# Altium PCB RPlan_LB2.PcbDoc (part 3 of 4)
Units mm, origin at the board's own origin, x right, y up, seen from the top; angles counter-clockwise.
Board outline 38.2 x 43.28 mm, 2 copper layers (Top Layer, Bottom Layer); 36 components, 100 nets, 269 pads, 31 vias.
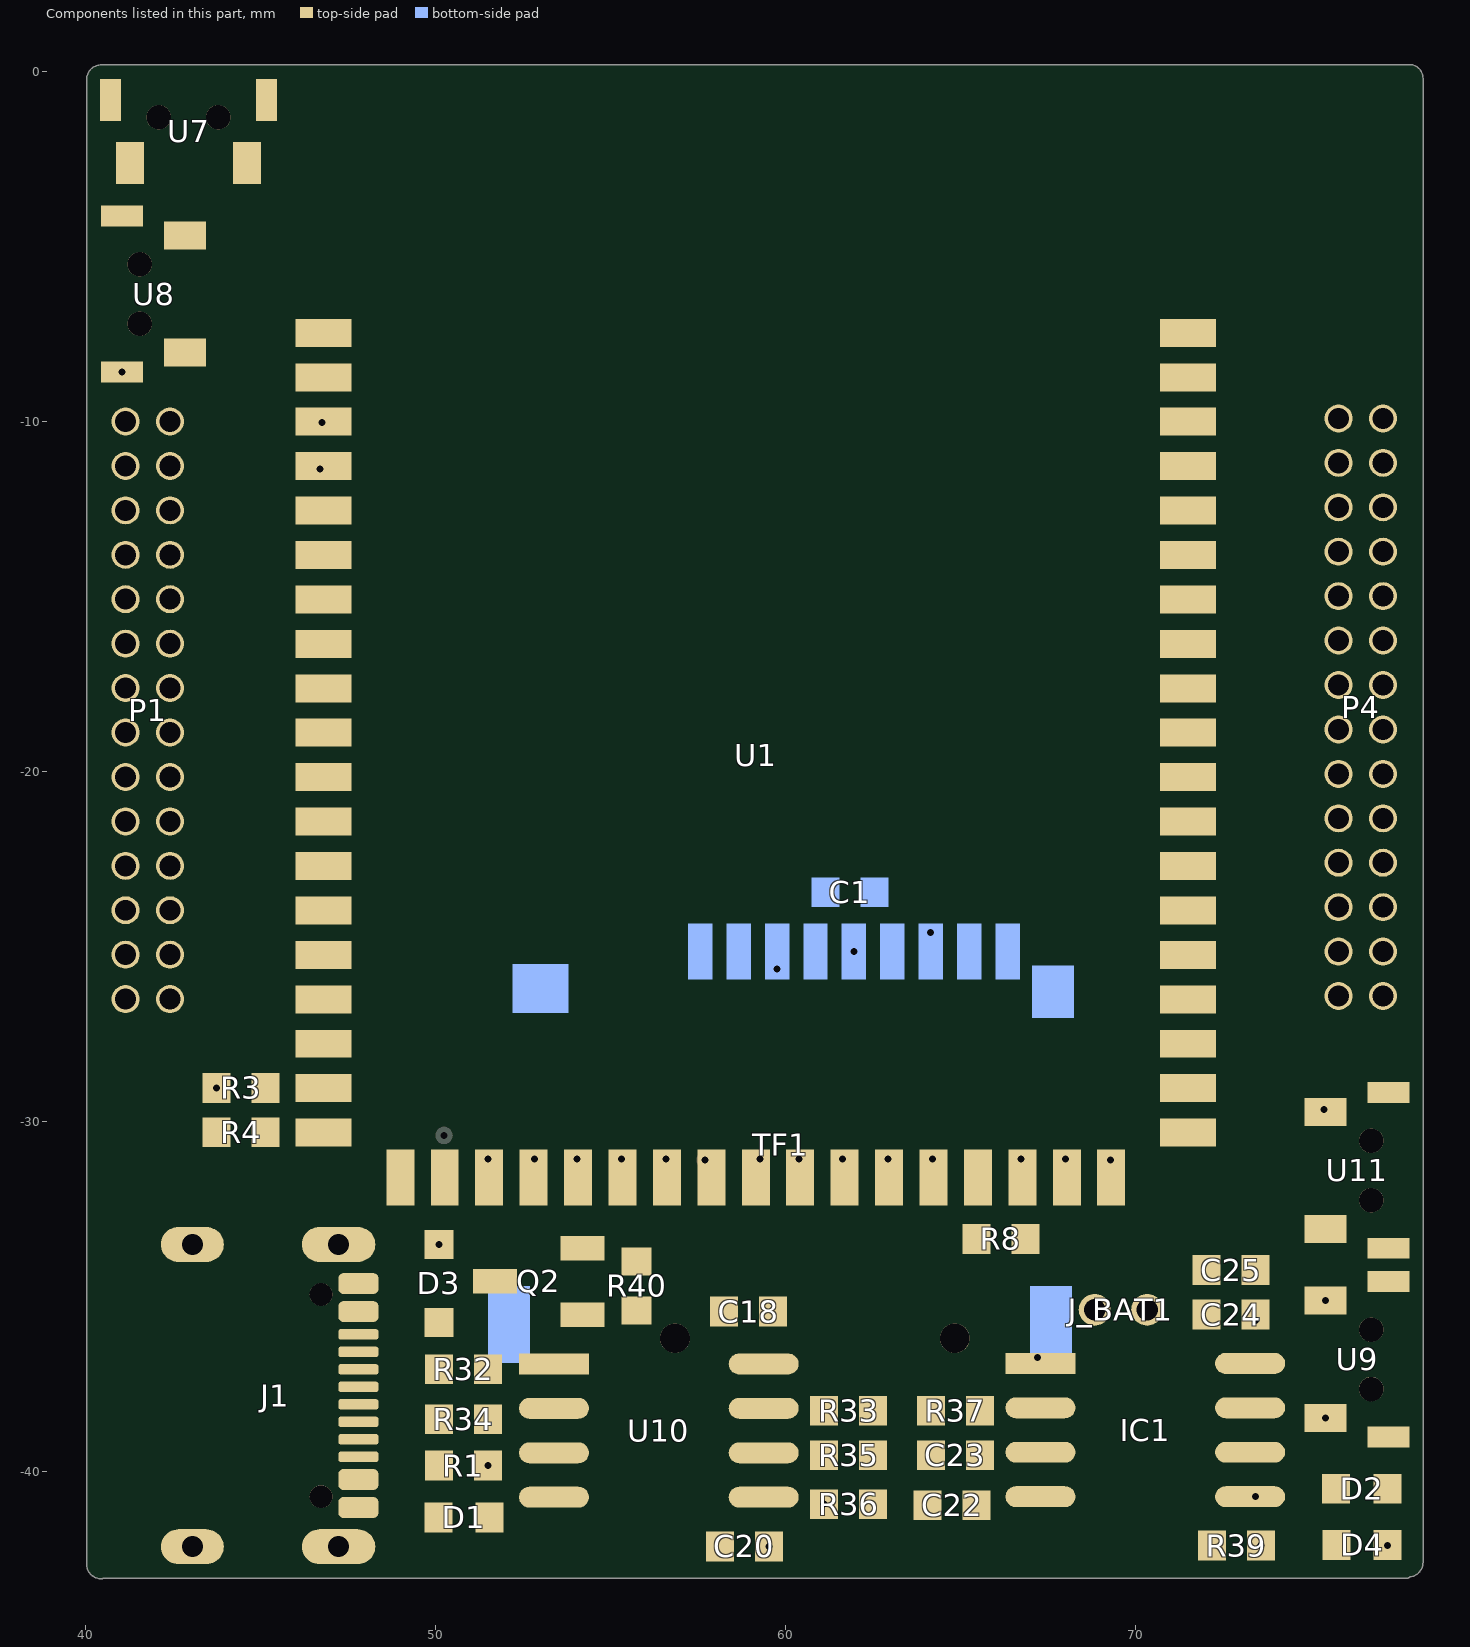
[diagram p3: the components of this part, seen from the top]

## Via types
v1: diameter 0.5, hole 0.3, Top Layer to Bottom Layer, 28 vias
v2: diameter 0.4, hole 0.2, Top Layer to Bottom Layer, 3 vias

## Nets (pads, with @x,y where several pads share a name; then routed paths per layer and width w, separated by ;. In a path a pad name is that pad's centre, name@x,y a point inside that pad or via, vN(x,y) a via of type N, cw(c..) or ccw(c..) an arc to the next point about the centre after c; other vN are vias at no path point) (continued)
copper on no net: (continued)
  Bottom Layer w0.025: 56.497,-15.715 57.386,-15.715 ; 56.497,-15.69 57.386,-15.69 ; 56.497,-15.664 57.386,-15.664 ; 56.497,-15.639 57.386,-15.639 ; 56.497,-15.613 57.386,-15.613 ; 56.497,-15.588 57.386,-15.588 ; 56.497,-15.563 57.386,-15.563 ; 56.497,-15.537 57.386,-15.537 ; 56.497,-15.512 57.386,-15.512 ; 56.497,-15.486 57.386,-15.486 ; 56.497,-15.461 57.386,-15.461 ; 56.497,-15.436 57.386,-15.436 ; 56.497,-15.41 57.183,-15.41 ; 56.497,-15.385 57.183,-15.385 ; 56.497,-15.359 57.183,-15.359 ; 56.497,-15.334 57.183,-15.334 ; 56.497,-15.309 57.183,-15.309 ; 56.497,-15.283 57.183,-15.283 ; 56.497,-15.258 57.183,-15.258 ; 56.497,-15.232 57.183,-15.232 ; 56.497,-15.207 57.183,-15.207 ; 56.497,-15.182 57.183,-15.182 ; 56.497,-15.156 57.183,-15.156 ; 56.497,-15.131 57.183,-15.131 ; 56.497,-14.775 56.852,-14.775 ; 56.497,-14.75 56.852,-14.75 ; 56.497,-14.724 56.852,-14.724 ; 56.497,-14.699 56.852,-14.699 ; 56.497,-14.674 56.852,-14.674 ; 56.497,-14.648 56.852,-14.648 ; 56.497,-14.623 56.852,-14.623 ; 56.497,-14.597 56.852,-14.597 ; 56.497,-14.572 56.852,-14.572 ; 56.497,-14.547 56.852,-14.547 ; 56.497,-14.521 56.852,-14.521 ; 56.497,-14.496 56.852,-14.496 ; 56.497,-14.47 56.852,-14.47 ; 56.497,-14.445 56.852,-14.445 ; 56.497,-14.115 56.852,-14.115 ; 56.497,-14.089 56.852,-14.089 ; 56.497,-14.064 56.852,-14.064 ; 56.497,-14.039 56.852,-14.039 ; 56.497,-14.013 56.852,-14.013 ; 56.497,-13.988 56.852,-13.988 ; 56.497,-13.962 56.852,-13.962 ; 56.497,-13.937 56.852,-13.937 ; 56.497,-13.912 56.852,-13.912 ; 56.497,-13.886 56.852,-13.886 ; 56.497,-13.861 56.852,-13.861 ; 56.497,-13.835 56.852,-13.835 ; 56.497,-13.81 56.852,-13.81 ; 56.497,-13.429 56.878,-13.429 ; 56.497,-13.404 56.852,-13.404 ; 56.497,-13.378 56.852,-13.378 ; 56.497,-13.353 56.852,-13.353 ; 56.497,-13.327 56.852,-13.327 ; 56.497,-13.302 56.852,-13.302 ; 56.497,-13.277 56.852,-13.277 ; 56.497,-13.251 56.852,-13.251 ; 56.497,-13.226 56.852,-13.226 ; 56.497,-13.2 56.852,-13.2 ; 56.497,-13.175 56.852,-13.175 ; 56.497,-13.15 56.852,-13.15 ; 56.497,-12.743 56.852,-12.743 ; 56.497,-12.718 56.852,-12.718 ; 56.497,-12.692 56.852,-12.692 ; 56.497,-12.667 56.852,-12.667 ; 56.497,-12.642 56.852,-12.642 ; 56.497,-12.616 56.852,-12.616 ; 56.497,-12.591 56.852,-12.591 ; 56.497,-12.565 56.852,-12.565 ; 56.497,-12.54 56.852,-12.54 ; 56.497,-12.515 56.852,-12.515 ; 56.497,-12.489 56.852,-12.489 ; 56.497,-12.464 56.852,-12.464 ; 56.802,-21.405 57.183,-21.405 ; 56.802,-21.379 57.183,-21.379 ; 56.802,-21.252 57.183,-21.252 ; 56.802,-21.227 57.183,-21.227 ; 56.802,-21.125 57.183,-21.125 ; 56.802,-19.525 57.183,-19.525 ; 56.802,-19.5 57.183,-19.5 ; 56.802,-19.474 57.183,-19.474 ; 56.802,-18.738 57.843,-18.738 ; 56.802,-18.712 57.843,-18.712 ; 56.802,-18.611 57.843,-18.611 ; 56.802,-18.534 57.843,-18.534 ; 56.802,-18.509 57.843,-18.509 ; 56.802,-18.484 57.843,-18.484 ; 56.802,-18.458 57.843,-18.458 ; 56.802,-12.108 57.183,-12.108 ; 56.802,-12.083 57.183,-12.083 ; 56.802,-11.829 57.183,-11.829 ; 56.802,-11.803 59.164,-11.803 ; 56.802,-11.778 59.164,-11.778 ; 56.802,-11.448 57.538,-11.448 ; 56.802,-11.422 57.538,-11.422 ; 56.802,-11.397 57.538,-11.397 ; 56.802,-11.194 57.538,-11.194 ; 56.802,-11.168 57.538,-11.168 ; 56.802,-11.143 57.538,-11.143 ; 56.802,-10.432 58.529,-10.432 ; 56.802,-10.406 58.529,-10.406 ; 56.852,-21.354 57.183,-21.354 ; 56.852,-21.328 57.183,-21.328 ; 56.852,-21.303 57.183,-21.303 ; 56.852,-21.278 57.183,-21.278 ; 56.852,-21.201 57.183,-21.201 ; 56.852,-21.176 57.183,-21.176 ; 56.852,-21.151 57.183,-21.151 ; 56.852,-20.058 57.183,-20.058 ; 56.852,-20.033 57.183,-20.033 ; 56.852,-20.008 57.183,-20.008 ; 56.852,-19.982 57.183,-19.982 ; 56.852,-19.957 57.183,-19.957 ; 56.852,-19.931 57.183,-19.931 ; 56.852,-19.906 57.183,-19.906 ; 56.852,-19.881 57.183,-19.881 ; 56.852,-19.855 57.183,-19.855 ; 56.852,-19.83 57.183,-19.83 ; 56.852,-19.804 57.183,-19.804 ; 56.852,-19.779 57.183,-19.779 ; 56.852,-19.754 57.183,-19.754 ; 56.852,-19.728 57.183,-19.728 ; 56.852,-19.703 57.183,-19.703 ; 56.852,-19.677 57.183,-19.677 ; 56.852,-19.652 57.183,-19.652 ; 56.852,-19.627 57.183,-19.627 ; 56.852,-19.601 57.183,-19.601 ; 56.852,-19.576 57.183,-19.576 ; 56.852,-19.55 57.183,-19.55 ; 56.852,-18.687 57.843,-18.687 ; 56.852,-18.661 57.843,-18.661 ; 56.852,-18.636 57.843,-18.636 ; 56.852,-18.585 57.843,-18.585 ; 56.852,-18.56 57.843,-18.56 ; 56.852,-12.057 57.183,-12.057 ; 56.852,-12.032 57.183,-12.032 ; 56.852,-12.007 57.183,-12.007 ; 56.852,-11.981 57.183,-11.981 ; 56.852,-11.956 57.183,-11.956 ; 56.852,-11.93 57.183,-11.93 ; 56.852,-11.905 57.183,-11.905 ; 56.852,-11.88 57.183,-11.88 ; 56.852,-11.854 57.183,-11.854 ; 56.852,-11.372 57.538,-11.372 ; 56.852,-11.346 57.538,-11.346 ; 56.852,-11.321 57.538,-11.321 ; 56.852,-11.295 57.538,-11.295 ; 56.852,-11.27 57.538,-11.27 ; 56.852,-11.245 57.538,-11.245 ; 56.852,-11.219 57.538,-11.219 ; 56.852,-10.457 58.529,-10.457 ; 56.852,-10.381 58.529,-10.381 ; 56.852,-10.356 58.529,-10.356 ; 56.852,-10.33 58.529,-10.33 ; 56.852,-10.305 58.529,-10.305 ; 56.852,-10.279 58.529,-10.279 ; 56.852,-10.254 58.529,-10.254 ; 56.852,-10.229 58.529,-10.229 ; 56.852,-10.203 58.529,-10.203 ; 56.852,-10.178 58.529,-10.178 ; 56.852,-10.152 58.529,-10.152 ; 56.852,-10.127 59.85,-10.127 ; 56.852,-10.102 59.85,-10.102 ; 57.157,-22.09 58.173,-22.09 ; 57.157,-22.065 58.173,-22.065 ; 57.157,-22.04 58.173,-22.04 ; 57.157,-22.014 58.173,-22.014 ; 57.157,-21.989 58.173,-21.989 ; 57.157,-21.963 58.173,-21.963 ; 57.157,-21.938 58.173,-21.938 ; 57.157,-21.913 58.173,-21.913 ; 57.157,-21.887 58.173,-21.887 ; 57.157,-21.862 58.173,-21.862 ; 57.157,-21.836 58.173,-21.836 ; 57.157,-21.811 58.173,-21.811 ; 57.157,-21.786 58.173,-21.786 ; 57.157,-21.76 58.173,-21.76 ; 57.157,-21.049 57.538,-21.049 ; 57.157,-21.024 57.538,-21.024 ; 57.157,-20.998 57.538,-20.998 ; 57.157,-20.973 57.538,-20.973 ; 57.157,-20.947 57.538,-20.947 ; 57.157,-20.922 57.538,-20.922 ; 57.157,-20.897 57.538,-20.897 ; 57.157,-20.871 57.538,-20.871 ; 57.157,-20.846 57.538,-20.846 ; 57.157,-20.82 57.538,-20.82 ; 57.157,-20.795 57.538,-20.795 ; 57.157,-20.77 57.538,-20.77 ; 57.157,-20.414 57.538,-20.414 ; 57.157,-20.389 57.538,-20.389 ; 57.157,-20.363 57.538,-20.363 ; 57.157,-20.338 57.538,-20.338 ; 57.157,-20.312 57.538,-20.312 ; 57.157,-20.287 57.538,-20.287 ; 57.157,-20.262 57.538,-20.262 ; 57.157,-20.236 57.538,-20.236 ; 57.157,-20.211 57.538,-20.211 ; 57.157,-20.185 57.538,-20.185 ; 57.157,-20.16 57.538,-20.16 ; 57.157,-20.135 57.538,-20.135 ; 57.157,-17.747 57.538,-17.747 ; 57.157,-17.722 57.538,-17.722 ; 57.157,-17.696 57.538,-17.696 ; 57.157,-17.671 57.538,-17.671 ; 57.157,-17.645 57.538,-17.645 ; 57.157,-17.62 57.538,-17.62 ; 57.157,-17.595 57.538,-17.595 ; 57.157,-17.569 57.538,-17.569 ; 57.157,-17.544 57.538,-17.544 ; 57.157,-17.518 57.538,-17.518 ; 57.157,-17.493 57.538,-17.493 ; 57.157,-17.468 57.538,-17.468 ; 57.157,-16.756 57.386,-16.756 ; 57.157,-16.731 57.386,-16.731 ; 57.157,-16.706 57.386,-16.706 ; 57.157,-16.68 57.386,-16.68 ; 57.157,-16.655 57.386,-16.655 ; 57.157,-16.629 57.386,-16.629 ; 57.157,-16.604 57.386,-16.604 ; 57.157,-16.579 57.386,-16.579 ; 57.157,-16.553 57.386,-16.553 ; 57.157,-16.528 57.386,-16.528 ; 57.157,-16.502 57.386,-16.502 ; 57.157,-16.477 57.386,-16.477 ; 57.157,-15.08 57.386,-15.08 ; 57.157,-15.055 57.386,-15.055 ; 57.157,-15.029 57.386,-15.029 ; 57.157,-15.004 57.386,-15.004 ; 57.157,-14.978 57.386,-14.978 ; 57.157,-14.953 57.386,-14.953 ; 57.157,-14.928 57.386,-14.928 ; 57.157,-14.902 57.386,-14.902 ; 57.157,-14.877 57.386,-14.877 ; 57.157,-14.851 57.386,-14.851 ; 57.157,-14.826 57.386,-14.826 ; 57.157,-14.801 57.386,-14.801 ; 57.157,-14.775 57.386,-14.775 ; 57.157,-14.75 57.386,-14.75 ; 57.157,-14.724 57.386,-14.724 ; 57.157,-14.699 57.386,-14.699 ; 57.157,-14.674 57.386,-14.674 ; 57.157,-14.648 57.411,-14.648 ; 57.157,-14.623 57.411,-14.623 ; 57.157,-14.597 57.411,-14.597 ; 57.157,-14.572 57.462,-14.572 ; 57.157,-14.547 57.462,-14.547 ; 57.157,-14.521 57.462,-14.521 ; 57.157,-14.496 57.487,-14.496 ; 57.157,-14.47 57.538,-14.47 ; 57.157,-14.445 57.538,-14.445 ; 57.157,-13.429 57.843,-13.429 ; 57.157,-13.404 57.843,-13.404 ; 57.157,-13.378 57.843,-13.378 ; 57.157,-13.353 57.843,-13.353 ; 57.157,-13.327 57.843,-13.327 ; 57.157,-13.302 57.843,-13.302 ; 57.157,-13.277 57.843,-13.277 ; 57.157,-13.251 57.843,-13.251 ; 57.157,-13.226 57.843,-13.226 ; 57.157,-13.2 57.843,-13.2 ; 57.157,-13.175 57.843,-13.175 ; 57.157,-13.15 57.843,-13.15 ; 57.157,-12.743 57.843,-12.743 ; 57.157,-12.718 57.843,-12.718 ; 57.157,-12.692 57.843,-12.692 ; 57.157,-12.667 57.843,-12.667 ; 57.157,-12.642 57.843,-12.642 ; 57.157,-12.616 57.843,-12.616 ; 57.157,-12.591 57.843,-12.591 ; 57.157,-12.565 57.843,-12.565 ; 57.157,-12.54 57.843,-12.54 ; 57.157,-12.515 57.843,-12.515 ; 57.157,-12.489 57.843,-12.489 ; 57.157,-12.464 57.843,-12.464 ; 57.157,-11.753 57.538,-11.753 ; 57.157,-11.727 57.538,-11.727 ; 57.157,-11.702 57.538,-11.702 ; 57.157,-11.676 57.538,-11.676 ; 57.157,-11.651 57.538,-11.651 ; 57.157,-11.626 57.538,-11.626 ; 57.157,-11.6 57.538,-11.6 ; 57.157,-11.575 57.538,-11.575 ; 57.157,-11.549 57.538,-11.549 ; 57.157,-11.524 57.538,-11.524 ; 57.157,-11.499 57.538,-11.499 ; 57.157,-11.473 57.538,-11.473 ; 57.157,-10.813 57.538,-10.813 ; 57.157,-10.787 57.538,-10.787 ; 57.157,-10.762 57.538,-10.762 ; 57.157,-10.737 57.538,-10.737 ; 57.157,-10.711 57.538,-10.711 ; 57.157,-10.686 57.538,-10.686 ; 57.157,-10.66 57.538,-10.66 ; 57.157,-10.635 57.538,-10.635 ; 57.157,-10.61 57.538,-10.61 ; 57.157,-10.584 57.538,-10.584 ; 57.157,-10.559 57.538,-10.559 ; 57.157,-10.533 57.538,-10.533 ; 57.157,-10.508 57.538,-10.508 ; 57.157,-10.483 57.538,-10.483 ; 57.487,-21.735 57.868,-21.735 ; 57.487,-21.709 57.843,-21.709 ; 57.487,-21.684 57.843,-21.684 ; 57.487,-21.659 57.843,-21.659 ; 57.487,-21.633 57.843,-21.633 ; 57.487,-21.608 57.843,-21.608 ; 57.487,-21.582 57.843,-21.582 ; 57.487,-21.557 57.843,-21.557 ; 57.487,-21.532 57.843,-21.532 ; 57.487,-21.506 57.843,-21.506 ; 57.487,-21.481 57.843,-21.481 ; 57.487,-21.455 57.843,-21.455 ; 57.487,-21.43 57.843,-21.43 ; 57.487,-21.405 57.843,-21.405 ; 57.487,-21.379 57.843,-21.379 ; 57.487,-21.354 57.843,-21.354 ; 57.487,-21.328 57.843,-21.328 ; 57.487,-21.303 57.843,-21.303 ; 57.487,-21.278 57.843,-21.278 ; 57.487,-21.252 57.843,-21.252 ; 57.487,-21.227 57.843,-21.227 ; 57.487,-21.201 57.843,-21.201 ; 57.487,-21.176 57.843,-21.176 ; 57.487,-21.151 57.843,-21.151 ; 57.487,-21.125 57.843,-21.125 ; 57.487,-19.754 59.519,-19.754 ; 57.487,-19.728 58.529,-19.728 ; 57.487,-19.703 58.529,-19.703 ; 57.487,-19.677 58.529,-19.677 ; 57.487,-19.652 58.529,-19.652 ; 57.487,-19.627 58.529,-19.627 ; 57.487,-19.601 58.529,-19.601 ; 57.487,-19.576 58.529,-19.576 ; 57.487,-19.55 58.529,-19.55 ; 57.487,-19.525 58.529,-19.525 ; 57.487,-19.5 58.529,-19.5 ; 57.487,-19.474 58.529,-19.474 ; 57.487,-14.42 57.564,-14.42 ; 57.487,-14.394 57.64,-14.394 ; 57.487,-14.369 57.64,-14.369 ; 57.487,-14.343 57.716,-14.343 ; 57.487,-14.318 57.843,-14.318 ; 57.487,-14.293 57.843,-14.293 ; 57.487,-14.267 57.843,-14.267 ; 57.487,-14.242 57.843,-14.242 ; 57.487,-14.216 57.843,-14.216 ; 57.487,-14.191 57.843,-14.191 ; 57.487,-14.166 57.843,-14.166 ; 57.487,-14.14 57.843,-14.14 ; 57.487,-14.115 57.843,-14.115 ; 57.487,-14.089 57.843,-14.089 ; 57.487,-14.064 57.843,-14.064 ; 57.487,-14.039 57.843,-14.039 ; 57.487,-14.013 57.843,-14.013 ; 57.487,-13.988 57.843,-13.988 ; 57.487,-13.962 57.843,-13.962 ; 57.487,-13.937 57.843,-13.937 ; 57.487,-13.912 57.843,-13.912 ; 57.487,-13.886 57.843,-13.886 ; 57.487,-13.861 57.843,-13.861 ; 57.487,-13.835 57.843,-13.835 ; 57.487,-13.81 57.843,-13.81 ; 57.487,-12.108 57.843,-12.108 ; 57.487,-12.083 57.843,-12.083 ; 57.487,-12.057 57.843,-12.057 ; 57.487,-12.032 57.843,-12.032 ; 57.487,-12.007 57.843,-12.007 ; 57.487,-11.981 57.843,-11.981 ; 57.487,-11.956 57.843,-11.956 ; 57.487,-11.93 57.843,-11.93 ; 57.487,-11.905 57.843,-11.905 ; 57.487,-11.88 57.843,-11.88 ; 57.487,-11.854 57.843,-11.854 ; 57.487,-11.829 57.843,-11.829 ; 57.614,-15.537 57.843,-15.537 ; 57.614,-15.512 57.843,-15.512 ; 57.614,-15.486 57.691,-15.486 ; 57.614,-15.461 57.64,-15.461 ; 57.614,-15.436 57.64,-15.436 ; 57.64,-15.563 57.792,-15.563 ; 57.691,-15.766 57.716,-15.766 ; 57.691,-15.74 57.716,-15.74 ; 57.691,-15.715 57.767,-15.715 ; 57.691,-15.69 57.767,-15.69 ; 57.691,-15.664 57.767,-15.664 ; 57.691,-15.639 57.767,-15.639 ; 57.691,-15.613 57.767,-15.613 ; 57.691,-15.588 57.767,-15.588 ; 57.767,-15.486 57.843,-15.486 ; 57.767,-15.461 57.843,-15.461 ; 57.767,-15.436 57.843,-15.436 ; 57.792,-17.62 58.173,-17.62 ; 57.792,-17.595 58.173,-17.595 ; 57.792,-17.569 58.173,-17.569 ; 57.843,-20.439 58.834,-20.439 ; 57.843,-20.414 58.173,-20.414 ; 57.843,-20.389 58.173,-20.389 ; 57.843,-20.363 58.173,-20.363 ; 57.843,-20.338 58.173,-20.338 ; 57.843,-20.312 58.173,-20.312 ; 57.843,-20.287 58.173,-20.287 ; 57.843,-20.262 58.173,-20.262 ; 57.843,-20.236 58.173,-20.236 ; 57.843,-20.211 58.173,-20.211 ; 57.843,-20.185 58.173,-20.185 ; 57.843,-20.16 58.173,-20.16 ; 57.843,-20.135 58.173,-20.135 ; 57.843,-20.109 58.173,-20.109 ; 57.843,-20.084 58.173,-20.084 ; 57.843,-17.747 58.173,-17.747 ; 57.843,-17.722 58.173,-17.722 ; 57.843,-17.696 58.173,-17.696 ; 57.843,-17.671 58.173,-17.671 ; 57.843,-17.645 58.173,-17.645 ; 57.843,-13.099 58.834,-13.099 ; 57.843,-13.073 58.834,-13.073 ; 57.843,-13.048 58.834,-13.048 ; 57.843,-13.023 58.834,-13.023 ; 57.843,-12.997 58.834,-12.997 ; 57.843,-12.972 58.834,-12.972 ; 57.843,-12.946 58.834,-12.946 ; 57.843,-12.921 58.834,-12.921 ; 57.843,-12.896 58.834,-12.896 ; 57.843,-12.87 58.834,-12.87 ; 57.843,-12.845 58.834,-12.845 ; 57.843,-12.819 58.834,-12.819 ; 57.843,-11.753 59.164,-11.753 ; 57.843,-11.727 59.164,-11.727 ; 57.843,-11.702 59.164,-11.702 ; 57.843,-11.676 59.164,-11.676 ; 57.843,-11.651 59.164,-11.651 ; 57.843,-11.626 59.164,-11.626 ; 57.843,-11.6 59.164,-11.6 ; 57.843,-11.575 59.164,-11.575 ; 57.843,-11.549 59.164,-11.549 ; 57.843,-11.524 59.164,-11.524 ; 57.843,-11.499 59.164,-11.499 ; 57.843,-11.473 59.164,-11.473 ; 57.843,-11.448 59.519,-11.448 ; 57.868,-15.715 57.945,-15.715 ; 57.868,-15.69 57.945,-15.69 ; 57.868,-15.664 57.945,-15.664 ; 57.868,-15.639 57.945,-15.639 ; 57.868,-15.613 58.072,-15.613 ; 57.868,-15.588 58.072,-15.588 ; 57.868,-15.563 58.072,-15.563 ; 57.868,-15.537 57.945,-15.537 ; 57.868,-15.512 57.945,-15.512 ; 57.868,-15.486 57.945,-15.486 ; 57.868,-15.461 57.919,-15.461 ; 57.868,-15.436 57.919,-15.436 ; 57.919,-16.452 58.249,-16.452 ; 57.919,-16.426 58.249,-16.426 ; 57.919,-16.401 58.402,-16.401 ; 57.919,-16.071 58.3,-16.071 ; 57.919,-16.045 58.3,-16.045 ; 57.919,-16.02 58.173,-16.02 ; 57.919,-15.994 58.021,-15.994 ; 57.919,-15.969 58.021,-15.969 ; 57.919,-15.766 57.945,-15.766 ; 57.919,-15.74 57.945,-15.74 ; 57.945,-16.477 58.072,-16.477 ; 57.995,-16.096 58.402,-16.096 ; 57.995,-15.69 58.605,-15.69 ; 57.995,-15.664 58.605,-15.664 ; 57.995,-15.639 58.097,-15.639 ; 57.995,-15.537 58.097,-15.537 ; 57.995,-15.512 58.097,-15.512 ; 58.021,-15.486 58.224,-15.486 ; 58.072,-16.375 58.605,-16.375 ; 58.072,-16.35 58.605,-16.35 ; 58.072,-15.715 58.224,-15.715 ; 58.072,-15.461 58.173,-15.461 ; 58.072,-15.436 58.173,-15.436 ; 58.148,-21.43 59.164,-21.43 ; 58.148,-21.405 58.529,-21.405 ; 58.148,-21.379 58.529,-21.379 ; 58.148,-21.354 58.529,-21.354 ; 58.148,-21.328 58.529,-21.328 ; 58.148,-21.303 58.529,-21.303 ; 58.148,-21.278 58.529,-21.278 ; 58.148,-21.252 58.529,-21.252 ; 58.148,-21.227 58.529,-21.227 ; 58.148,-21.201 58.529,-21.201 ; 58.148,-21.176 58.529,-21.176 ; 58.148,-21.151 58.529,-21.151 ; 58.148,-21.125 58.529,-21.125 ; 58.148,-21.1 58.834,-21.1 ; 58.148,-21.074 58.834,-21.074 ; 58.148,-20.744 58.834,-20.744 ; 58.148,-20.719 58.834,-20.719 ; 58.148,-20.693 58.834,-20.693 ; 58.148,-20.668 58.834,-20.668 ; 58.148,-20.643 58.834,-20.643 ; 58.148,-20.617 58.834,-20.617 ; 58.148,-20.592 58.834,-20.592 ; 58.148,-20.566 58.834,-20.566 ; 58.148,-20.541 58.834,-20.541 ; 58.148,-20.516 58.834,-20.516 ; 58.148,-20.49 58.834,-20.49 ; 58.148,-20.465 58.834,-20.465 ; 58.148,-19.423 58.834,-19.423 ; 58.148,-19.398 58.834,-19.398 ; 58.148,-19.373 58.834,-19.373 ; 58.148,-19.347 58.834,-19.347 ; 58.148,-19.322 58.834,-19.322 ; 58.148,-19.296 58.834,-19.296 ; 58.148,-19.271 58.834,-19.271 ; 58.148,-19.246 58.834,-19.246 ; 58.148,-19.22 58.834,-19.22 ; 58.148,-19.195 58.834,-19.195 ; 58.148,-19.169 58.834,-19.169 ; 58.148,-19.144 58.834,-19.144 ; 58.148,-19.119 58.834,-19.119 ; 58.148,-19.093 58.834,-19.093 ; 58.148,-16.147 58.554,-16.147 ; 58.148,-16.121 58.554,-16.121 ; 58.148,-15.639 58.605,-15.639 ; 58.148,-15.613 58.224,-15.613 ; 58.148,-15.588 58.224,-15.588 ; 58.148,-15.563 58.224,-15.563 ; 58.148,-15.537 58.224,-15.537 ; 58.148,-15.512 58.224,-15.512 ; 58.148,-14.115 58.529,-14.115 ; 58.148,-14.089 58.529,-14.089 ; 58.148,-14.064 58.529,-14.064 ; 58.148,-14.039 58.529,-14.039 ; 58.148,-14.013 58.529,-14.013 ; 58.148,-13.988 58.529,-13.988 ; 58.148,-13.962 58.529,-13.962 ; 58.148,-13.937 58.529,-13.937 ; 58.148,-13.912 58.529,-13.912 ; 58.148,-13.886 58.529,-13.886 ; 58.148,-13.861 58.529,-13.861 ; 58.148,-13.835 58.529,-13.835 ; 58.148,-13.81 58.529,-13.81 ; 58.148,-13.785 58.529,-13.785 ; 58.148,-13.759 58.529,-13.759 ; 58.148,-13.734 58.529,-13.734 ; 58.148,-13.708 58.529,-13.708 ; 58.148,-13.683 58.529,-13.683 ; 58.148,-13.658 58.529,-13.658 ; 58.148,-13.632 58.529,-13.632 ; 58.148,-13.607 58.529,-13.607 ; 58.148,-13.581 58.529,-13.581 ; 58.148,-13.556 58.529,-13.556 ; 58.148,-13.531 58.529,-13.531 ; 58.148,-13.505 58.529,-13.505 ; 58.148,-13.48 58.834,-13.48 ; 58.148,-13.454 58.834,-13.454 ; 58.148,-13.429 58.834,-13.429 ; 58.148,-13.404 58.834,-13.404 ; 58.148,-13.378 58.834,-13.378 ; 58.148,-13.353 58.834,-13.353 ; 58.148,-13.327 58.834,-13.327 ; 58.148,-13.302 58.834,-13.302 ; 58.148,-13.277 58.834,-13.277 ; 58.148,-13.251 58.834,-13.251 ; 58.148,-13.226 58.834,-13.226 ; 58.148,-13.2 58.834,-13.2 ; 58.148,-13.175 58.834,-13.175 ; 58.148,-13.15 58.834,-13.15 ; 58.148,-12.743 59.164,-12.743 ; 58.148,-12.718 59.164,-12.718 ; 58.148,-12.692 59.164,-12.692 ; 58.148,-12.667 59.164,-12.667 ; 58.148,-12.642 59.164,-12.642 ; 58.148,-12.616 59.164,-12.616 ; 58.148,-12.591 59.164,-12.591 ; 58.148,-12.565 59.164,-12.565 ; 58.148,-12.54 59.164,-12.54 ; 58.148,-12.515 59.164,-12.515 ; 58.148,-12.489 59.164,-12.489 ; 58.148,-12.464 59.164,-12.464 ; 58.148,-12.438 59.519,-12.438 ; 58.148,-12.413 58.529,-12.413 ; 58.148,-12.388 58.529,-12.388 ; 58.148,-12.362 58.529,-12.362 ; 58.148,-12.337 58.529,-12.337 ; 58.148,-12.311 58.529,-12.311 ; 58.148,-12.286 58.529,-12.286 ; 58.148,-12.261 58.529,-12.261 ; 58.148,-12.235 58.529,-12.235 ; 58.148,-12.21 58.529,-12.21 ; 58.148,-12.184 58.529,-12.184 ; 58.148,-12.159 58.529,-12.159 ; 58.148,-12.134 58.529,-12.134 ; 58.148,-12.108 58.529,-12.108 ; 58.148,-12.083 58.529,-12.083 ; 58.148,-12.057 58.529,-12.057 ; 58.148,-12.032 58.529,-12.032 ; 58.148,-12.007 58.529,-12.007 ; 58.148,-11.981 58.529,-11.981 ; 58.148,-11.956 58.529,-11.956 ; 58.148,-11.93 58.529,-11.93 ; 58.148,-11.905 58.529,-11.905 ; 58.148,-11.88 58.529,-11.88 ; 58.148,-11.854 58.529,-11.854 ; 58.148,-11.829 58.529,-11.829 ; 58.148,-11.422 58.834,-11.422 ; 58.148,-11.397 58.834,-11.397 ; 58.148,-11.372 58.834,-11.372 ; 58.148,-11.346 58.834,-11.346 ; 58.148,-11.321 58.834,-11.321 ; 58.148,-11.295 58.834,-11.295 ; 58.148,-11.27 58.834,-11.27 ; 58.148,-11.245 58.834,-11.245 ; 58.148,-11.219 58.834,-11.219 ; 58.148,-11.194 58.834,-11.194 ; 58.148,-11.168 58.834,-11.168 ; 58.148,-11.143 58.834,-11.143 ; 58.148,-10.813 58.529,-10.813 ; 58.148,-10.787 58.529,-10.787 ; 58.148,-10.762 58.529,-10.762 ; 58.148,-10.737 58.529,-10.737 ; 58.148,-10.711 58.529,-10.711 ; 58.148,-10.686 58.529,-10.686 ; 58.148,-10.66 58.529,-10.66 ; 58.148,-10.635 58.529,-10.635 ; 58.148,-10.61 58.529,-10.61 ; 58.148,-10.584 58.529,-10.584 ; 58.148,-10.559 58.529,-10.559 ; 58.148,-10.533 58.529,-10.533 ; 58.148,-10.508 58.529,-10.508 ; 58.148,-10.483 58.529,-10.483 ; 58.224,-16.325 59.164,-16.325 ; 58.249,-16.172 58.681,-16.172 ; 58.3,-15.461 58.376,-15.461 ; 58.3,-15.436 58.376,-15.436 ; 58.3,-15.41 58.478,-15.41 ; 58.3,-15.385 58.478,-15.385 ; 58.3,-15.359 58.478,-15.359 ; 58.326,-15.766 58.453,-15.766 ; 58.326,-15.74 58.453,-15.74 ; 58.326,-15.715 58.453,-15.715 ; 58.326,-15.613 58.453,-15.613 ; 58.326,-15.588 58.453,-15.588 ; 58.326,-15.563 58.453,-15.563 ; 58.326,-15.537 58.402,-15.537 ; 58.326,-15.512 58.402,-15.512 ; 58.326,-15.486 58.402,-15.486 ; 58.376,-15.791 58.453,-15.791 ; 58.402,-16.299 59.088,-16.299 ; 58.402,-16.274 59.088,-16.274 ; 58.402,-16.223 59.215,-16.223 ; 58.402,-16.198 59.215,-16.198 ; 58.478,-21.786 60.154,-21.786 ; 58.478,-21.76 60.154,-21.76 ; 58.478,-21.735 59.164,-21.735 ; 58.478,-21.709 59.164,-21.709 ; 58.478,-21.684 59.164,-21.684 ; 58.478,-21.659 59.164,-21.659 ; 58.478,-21.633 59.164,-21.633 ; 58.478,-21.608 59.164,-21.608 ; 58.478,-21.582 59.164,-21.582 ; 58.478,-21.557 59.164,-21.557 ; 58.478,-21.532 59.164,-21.532 ; 58.478,-21.506 59.164,-21.506 ; 58.478,-21.481 59.164,-21.481 ; 58.478,-21.455 59.164,-21.455 ; 58.478,-21.049 58.834,-21.049 ; 58.478,-21.024 58.834,-21.024 ; 58.478,-20.998 58.834,-20.998 ; 58.478,-20.973 58.834,-20.973 ; 58.478,-20.947 58.834,-20.947 ; 58.478,-20.922 58.834,-20.922 ; 58.478,-20.897 58.834,-20.897 ; 58.478,-20.871 58.834,-20.871 ; 58.478,-20.846 58.834,-20.846 ; 58.478,-20.82 58.834,-20.82 ; 58.478,-20.795 58.834,-20.795 ; 58.478,-20.77 58.834,-20.77 ; 58.478,-20.414 58.834,-20.414 ; 58.478,-20.389 58.834,-20.389 ; 58.478,-20.363 58.834,-20.363 ; 58.478,-20.338 58.834,-20.338 ; 58.478,-20.312 58.834,-20.312 ; 58.478,-20.287 58.834,-20.287 ; 58.478,-20.262 58.834,-20.262 ; 58.478,-20.236 58.834,-20.236 ; 58.478,-20.211 58.834,-20.211 ; 58.478,-20.185 58.834,-20.185 ; 58.478,-20.16 58.834,-20.16 ; 58.478,-20.135 58.834,-20.135 ; 58.478,-20.109 59.519,-20.109 ; 58.478,-20.084 59.519,-20.084 ; 58.478,-20.058 59.519,-20.058 ; 58.478,-20.033 59.519,-20.033 ; 58.478,-20.008 59.519,-20.008 ; 58.478,-19.982 59.519,-19.982 ; 58.478,-19.957 59.519,-19.957 ; 58.478,-19.931 59.519,-19.931 ; 58.478,-19.906 59.519,-19.906 ; 58.478,-19.881 59.519,-19.881 ; 58.478,-19.855 59.519,-19.855 ; 58.478,-19.83 59.519,-19.83 ; 58.478,-19.804 59.519,-19.804 ; 58.478,-19.779 59.519,-19.779 ; 58.478,-19.068 58.834,-19.068 ; 58.478,-19.042 58.834,-19.042 ; 58.478,-19.017 58.834,-19.017 ; 58.478,-18.992 58.834,-18.992 ; 58.478,-18.966 58.834,-18.966 ; 58.478,-18.941 58.834,-18.941 ; 58.478,-18.915 58.834,-18.915 ; 58.478,-18.89 58.834,-18.89 ; 58.478,-18.865 58.834,-18.865 ; 58.478,-18.839 58.834,-18.839 ; 58.478,-18.814 58.834,-18.814 ; 58.478,-18.788 58.834,-18.788 ; 58.478,-18.763 61.831,-18.763 ; 58.478,-18.738 59.85,-18.738 ; 58.478,-18.712 59.85,-18.712 ; 58.478,-18.687 59.85,-18.687 ; 58.478,-18.661 59.85,-18.661 ; 58.478,-18.636 59.85,-18.636 ; 58.478,-18.611 59.85,-18.611 ; 58.478,-18.585 59.85,-18.585 ; 58.478,-18.56 59.85,-18.56 ; 58.478,-18.534 59.85,-18.534 ; 58.478,-18.509 59.85,-18.509 ; 58.478,-18.484 59.85,-18.484 ; 58.478,-18.458 59.85,-18.458 ; 58.478,-18.433 62.186,-18.433 ; 58.478,-18.407 62.186,-18.407 ; 58.478,-18.382 59.164,-18.382 ; 58.478,-18.357 59.164,-18.357 ; 58.478,-18.331 59.164,-18.331 ; 58.478,-18.306 59.164,-18.306 ; 58.478,-18.28 59.164,-18.28 ; 58.478,-18.255 59.164,-18.255 ; 58.478,-18.23 59.164,-18.23 ; 58.478,-18.204 59.164,-18.204 ; 58.478,-18.179 59.164,-18.179 ; 58.478,-18.153 59.164,-18.153 ; 58.478,-18.128 60.51,-18.128 ; 58.478,-18.103 60.51,-18.103 ; 58.478,-18.077 58.834,-18.077 ; 58.478,-18.052 58.834,-18.052 ; 58.478,-18.026 58.834,-18.026 ; 58.478,-18.001 58.834,-18.001 ; 58.478,-17.976 58.834,-17.976 ; 58.478,-17.95 58.834,-17.95 ; 58.478,-17.925 58.834,-17.925 ; 58.478,-17.899 58.834,-17.899 ; 58.478,-17.874 58.834,-17.874 ; 58.478,-17.849 58.834,-17.849 ; 58.478,-17.823 58.834,-17.823 ; 58.478,-17.798 58.834,-17.798 ; 58.478,-17.772 61.501,-17.772 ; 58.478,-17.747 60.154,-17.747 ; 58.478,-17.722 60.154,-17.722 ; 58.478,-17.696 60.154,-17.696 ; 58.478,-17.671 60.154,-17.671 ; 58.478,-17.645 60.154,-17.645 ; 58.478,-17.62 60.205,-17.62 ; 58.478,-17.595 60.154,-17.595 ; 58.478,-17.569 60.154,-17.569 ; 58.478,-15.461 58.605,-15.461 ; 58.478,-15.436 58.605,-15.436 ; 58.478,-10.076 59.164,-10.076 ; 58.478,-10.051 59.164,-10.051 ; 58.478,-10.025 59.164,-10.025 ; 58.478,-10 59.164,-10 ; 58.478,-9.975 59.164,-9.975 ; 58.478,-9.949 59.164,-9.949 ; 58.478,-9.924 59.164,-9.924 ; 58.478,-9.898 59.164,-9.898 ; 58.478,-9.873 59.164,-9.873 ; 58.478,-9.848 59.164,-9.848 ; 58.478,-9.822 59.164,-9.822 ; 58.478,-9.797 59.164,-9.797 ; 58.529,-16.248 59.164,-16.248 ; 58.529,-15.766 58.605,-15.766 ; 58.529,-15.74 58.605,-15.74 ; 58.529,-15.715 58.605,-15.715 ; 58.529,-15.537 58.681,-15.537 ; 58.529,-15.512 58.681,-15.512 ; 58.529,-15.486 58.63,-15.486 ; 58.554,-15.613 58.63,-15.613 ; 58.554,-15.588 58.63,-15.588 ; 58.554,-15.563 58.681,-15.563 ; 58.707,-15.766 59.062,-15.766 ; 58.707,-15.74 59.062,-15.74 ; 58.707,-15.715 59.062,-15.715 ; 58.707,-15.69 58.935,-15.69 ; 58.707,-15.664 58.935,-15.664 ; 58.707,-15.639 58.834,-15.639 ; 58.707,-15.613 58.783,-15.613 ; 58.707,-15.588 58.783,-15.588 ; 58.707,-15.563 59.138,-15.563 ; 58.757,-15.41 58.935,-15.41 ; 58.783,-15.537 59.138,-15.537 ; 58.783,-15.512 59.138,-15.512 ; 58.783,-15.461 58.935,-15.461 ; 58.783,-15.436 58.935,-15.436 ; 58.783,-15.385 58.935,-15.385 ; 58.783,-15.359 58.935,-15.359 ; 58.834,-19.728 59.519,-19.728 ; 58.834,-19.703 59.519,-19.703 ; 58.834,-19.677 59.519,-19.677 ; 58.834,-19.652 59.519,-19.652 ; 58.834,-19.627 59.519,-19.627 ; 58.834,-19.601 59.519,-19.601 ; 58.834,-19.576 59.519,-19.576 ; 58.834,-19.55 59.519,-19.55 ; 58.834,-19.525 59.519,-19.525 ; 58.834,-19.5 59.519,-19.5 ; 58.834,-19.474 59.519,-19.474 ; 58.834,-14.318 60.51,-14.318 ; 58.834,-14.293 60.51,-14.293 ; 58.834,-14.267 60.51,-14.267 ; 58.834,-14.242 60.51,-14.242 ; 58.834,-14.216 60.51,-14.216 ; 58.834,-14.191 60.51,-14.191 ; 58.834,-14.166 60.51,-14.166 ; 58.834,-14.14 60.51,-14.14 ; 58.834,-14.115 61.831,-14.115 ; 58.834,-12.413 59.519,-12.413 ; 58.834,-12.388 59.519,-12.388 ; 58.834,-12.362 59.519,-12.362 ; 58.834,-12.337 59.519,-12.337 ; 58.834,-12.311 59.519,-12.311 ; 58.834,-12.286 59.519,-12.286 ; 58.834,-12.261 59.519,-12.261 ; 58.834,-12.235 59.519,-12.235 ; 58.834,-12.21 59.519,-12.21 ; 58.834,-12.184 59.519,-12.184 ; 58.834,-12.159 59.519,-12.159 ; 58.834,-12.134 60.51,-12.134 ; 58.834,-12.108 59.164,-12.108 ; 58.834,-12.083 59.164,-12.083 ; 58.834,-12.057 59.164,-12.057 ; 58.834,-12.032 59.164,-12.032 ; 58.834,-12.007 59.164,-12.007 ; 58.834,-11.981 59.164,-11.981 ; 58.834,-11.956 59.164,-11.956 ; 58.834,-11.93 59.164,-11.93 ; 58.834,-11.905 59.164,-11.905 ; 58.834,-11.88 59.164,-11.88 ; 58.834,-11.854 59.164,-11.854 ; 58.834,-11.829 59.164,-11.829 ; 58.834,-10.813 59.85,-10.813 ; 58.834,-10.787 59.85,-10.787 ; 58.834,-10.762 59.85,-10.762 ; 58.834,-10.737 59.85,-10.737 ; 58.834,-10.711 59.85,-10.711 ; 58.834,-10.686 59.85,-10.686 ; 58.834,-10.66 59.85,-10.66 ; 58.834,-10.635 59.85,-10.635 ; 58.834,-10.61 59.85,-10.61 ; 58.834,-10.584 59.85,-10.584 ; 58.834,-10.559 59.85,-10.559 ; 58.834,-10.533 59.85,-10.533 ; 58.834,-10.508 59.85,-10.508 ; 58.834,-10.483 59.85,-10.483 ; 58.834,-10.457 59.85,-10.457 ; 58.859,-15.639 58.935,-15.639 ; 58.859,-15.613 59.138,-15.613 ; 58.859,-15.588 59.138,-15.588 ; 58.859,-15.486 58.935,-15.486 ; 58.935,-16.375 59.164,-16.375 ; 58.935,-16.35 59.164,-16.35 ; 58.986,-16.172 59.215,-16.172 ; 58.986,-15.69 59.062,-15.69 ; 58.986,-15.664 59.062,-15.664 ; 58.986,-15.639 59.062,-15.639 ; 59.062,-16.401 59.164,-16.401 ; 59.062,-15.486 59.138,-15.486 ; 59.164,-22.09 59.519,-22.09 ; 59.164,-22.065 59.519,-22.065 ; 59.164,-22.04 59.519,-22.04 ; 59.164,-22.014 59.519,-22.014 ; 59.164,-21.989 59.519,-21.989 ; 59.164,-21.963 59.519,-21.963 ; 59.164,-21.938 59.519,-21.938 ; 59.164,-21.913 59.519,-21.913 ; 59.164,-21.887 59.519,-21.887 ; 59.164,-21.862 59.519,-21.862 ; 59.164,-21.836 59.519,-21.836 ; 59.164,-21.811 59.519,-21.811 ; 59.164,-21.1 59.519,-21.1 ; 59.164,-21.074 59.519,-21.074 ; 59.164,-21.049 59.519,-21.049 ; 59.164,-21.024 59.519,-21.024 ; 59.164,-20.998 59.519,-20.998 ; 59.164,-20.973 59.519,-20.973 ; 59.164,-20.947 59.519,-20.947 ; 59.164,-20.922 59.519,-20.922 ; 59.164,-20.897 59.519,-20.897 ; 59.164,-20.871 59.519,-20.871 ; 59.164,-20.846 59.519,-20.846 ; 59.164,-20.82 59.519,-20.82 ; 59.164,-20.795 59.519,-20.795 ; 59.164,-20.77 59.519,-20.77 ; 59.164,-20.439 62.517,-20.439 ; 59.164,-20.414 59.519,-20.414 ; 59.164,-20.389 59.519,-20.389 ; 59.164,-20.363 59.519,-20.363 ; 59.164,-20.338 59.519,-20.338 ; 59.164,-20.312 59.519,-20.312 ; 59.164,-20.287 59.519,-20.287 ; 59.164,-20.262 59.519,-20.262 ; 59.164,-20.236 59.519,-20.236 ; 59.164,-20.211 59.519,-20.211 ; 59.164,-20.185 59.519,-20.185 ; 59.164,-20.16 59.519,-20.16 ; 59.164,-20.135 59.519,-20.135 ; 59.164,-19.119 65.158,-19.119 ; 59.164,-19.093 65.158,-19.093 ; 59.164,-19.068 59.519,-19.068 ; 59.164,-19.042 59.519,-19.042 ; 59.164,-19.017 59.519,-19.017 ; 59.164,-18.992 59.519,-18.992 ; 59.164,-18.966 59.519,-18.966 ; 59.164,-18.941 59.519,-18.941 ; 59.164,-18.915 59.519,-18.915 ; 59.164,-18.89 59.519,-18.89 ; 59.164,-18.865 59.519,-18.865 ; 59.164,-18.839 59.519,-18.839 ; 59.164,-18.814 59.519,-18.814 ; 59.164,-18.788 59.519,-18.788 ; 59.164,-18.077 59.519,-18.077 ; 59.164,-18.052 59.519,-18.052 ; 59.164,-18.026 59.519,-18.026 ; 59.164,-18.001 59.519,-18.001 ; 59.164,-17.976 59.519,-17.976 ; 59.164,-17.95 59.519,-17.95 ; 59.164,-17.925 59.519,-17.925 ; 59.164,-17.899 59.519,-17.899 ; 59.164,-17.874 59.519,-17.874 ; 59.164,-17.849 59.519,-17.849 ; 59.164,-17.823 59.519,-17.823 ; 59.164,-17.798 59.519,-17.798 ; 59.164,-14.089 60.154,-14.089 ; 59.164,-14.064 60.154,-14.064 ; 59.164,-14.039 60.154,-14.039 ; 59.164,-14.013 60.154,-14.013 ; 59.164,-13.988 60.154,-13.988 ; 59.164,-13.962 60.154,-13.962 ; 59.164,-13.937 60.154,-13.937 ; 59.164,-13.912 60.154,-13.912 ; 59.164,-13.886 60.154,-13.886 ; 59.164,-13.861 60.154,-13.861 ; 59.164,-13.835 60.154,-13.835 ; 59.164,-13.81 60.154,-13.81 ; 59.164,-13.785 60.154,-13.785 ; 59.164,-13.759 60.154,-13.759 ; 59.164,-13.734 60.154,-13.734 ; 59.164,-13.708 60.154,-13.708 ; 59.164,-13.683 60.154,-13.683 ; 59.164,-13.658 60.154,-13.658 ; 59.164,-13.632 60.154,-13.632 ; 59.164,-13.607 60.154,-13.607 ; 59.164,-13.581 60.154,-13.581 ; 59.164,-13.556 60.154,-13.556 ; 59.164,-13.531 60.154,-13.531 ; 59.164,-13.505 60.154,-13.505 ; 59.164,-13.48 60.154,-13.48 ; 59.164,-13.454 60.154,-13.454 ; 59.164,-13.429 59.519,-13.429 ; 59.164,-13.404 59.519,-13.404 ; 59.164,-13.378 59.519,-13.378 ; 59.164,-13.353 59.519,-13.353 ; 59.164,-13.327 59.519,-13.327 ; 59.164,-13.302 59.519,-13.302 ; 59.164,-13.277 59.519,-13.277 ; 59.164,-13.251 59.519,-13.251 ; 59.164,-13.226 59.519,-13.226 ; 59.164,-13.2 59.519,-13.2 ; 59.164,-13.175 59.519,-13.175 ; 59.164,-13.15 59.519,-13.15 ; 59.164,-13.124 59.519,-13.124 ; 59.164,-11.422 59.519,-11.422 ; 59.164,-11.397 59.519,-11.397 ; 59.164,-11.372 59.519,-11.372 ; 59.164,-11.346 59.519,-11.346 ; 59.164,-11.321 59.519,-11.321 ; 59.164,-11.295 59.519,-11.295 ; 59.164,-11.27 59.519,-11.27 ; 59.164,-11.245 59.519,-11.245 ; 59.164,-11.219 59.519,-11.219 ; 59.164,-11.194 59.519,-11.194 ; 59.164,-11.168 59.519,-11.168 ; 59.164,-11.143 59.519,-11.143 ; 59.164,-10.432 59.85,-10.432 ; 59.164,-10.406 59.85,-10.406 ; 59.164,-10.381 59.85,-10.381 ; 59.164,-10.356 59.85,-10.356 ; 59.164,-10.33 59.85,-10.33 ; 59.164,-10.305 59.85,-10.305 ; 59.164,-10.279 59.85,-10.279 ; 59.164,-10.254 59.85,-10.254 ; 59.164,-10.229 59.85,-10.229 ; 59.164,-10.203 59.85,-10.203 ; 59.164,-10.178 59.85,-10.178 ; 59.164,-10.152 59.85,-10.152 ; 59.215,-15.842 59.24,-15.842 ; 59.215,-15.817 59.24,-15.817 ; 59.215,-15.791 59.24,-15.791 ; 59.215,-15.766 59.24,-15.766 ; 59.215,-15.74 59.24,-15.74 ; 59.215,-15.715 59.291,-15.715 ; 59.215,-15.69 59.291,-15.69 ; 59.215,-15.664 59.291,-15.664 ; 59.215,-15.639 59.291,-15.639 ; 59.24,-16.02 59.291,-16.02 ; 59.24,-15.994 59.291,-15.994 ; 59.24,-15.969 59.291,-15.969 ; 59.24,-15.613 59.316,-15.613 ; 59.24,-15.588 59.316,-15.588 ; 59.24,-15.563 59.316,-15.563 ; 59.291,-15.766 59.367,-15.766 ; 59.291,-15.74 59.367,-15.74 ; 59.291,-15.537 59.367,-15.537 ; 59.291,-15.512 59.367,-15.512 ; 59.316,-15.486 59.469,-15.486 ; 59.367,-15.69 59.392,-15.69 ; 59.367,-15.664 59.392,-15.664 ; 59.367,-15.639 59.443,-15.639 ; 59.367,-15.563 59.392,-15.563 ; 59.367,-15.461 59.519,-15.461 ; 59.367,-15.436 59.519,-15.436 ; 59.443,-15.791 59.596,-15.791 ; 59.443,-15.715 59.519,-15.715 ; 59.443,-15.69 59.519,-15.69 ; 59.443,-15.664 59.519,-15.664 ; 59.443,-15.41 59.672,-15.41 ; 59.469,-21.735 59.85,-21.735 ; 59.469,-21.709 59.85,-21.709 ; 59.469,-21.684 59.85,-21.684 ; 59.469,-21.659 59.85,-21.659 ; 59.469,-21.633 59.85,-21.633 ; 59.469,-21.608 59.85,-21.608 ; 59.469,-21.582 59.85,-21.582 ; 59.469,-21.557 59.85,-21.557 ; 59.469,-21.532 59.85,-21.532 ; 59.469,-21.506 59.85,-21.506 ; 59.469,-21.481 59.85,-21.481 ; 59.469,-21.455 59.85,-21.455 ; 59.469,-21.43 59.85,-21.43 ; 59.469,-20.744 60.84,-20.744 ; 59.469,-20.719 60.84,-20.719 ; 59.469,-20.693 60.84,-20.693 ; 59.469,-20.668 60.84,-20.668 ; 59.469,-20.643 60.84,-20.643 ; 59.469,-20.617 60.84,-20.617 ; 59.469,-20.592 60.84,-20.592 ; 59.469,-20.566 60.84,-20.566 ; 59.469,-20.541 60.84,-20.541 ; 59.469,-20.516 60.84,-20.516 ; 59.469,-20.49 60.84,-20.49 ; 59.469,-20.465 60.84,-20.465 ; 59.469,-19.423 59.85,-19.423 ; 59.469,-19.398 59.85,-19.398 ; 59.469,-19.373 59.85,-19.373 ; 59.469,-19.347 59.85,-19.347 ; 59.469,-19.322 59.85,-19.322 ; 59.469,-19.296 59.85,-19.296 ; 59.469,-19.271 59.85,-19.271 ; 59.469,-19.246 59.85,-19.246 ; 59.469,-19.22 59.85,-19.22 ; 59.469,-19.195 59.85,-19.195 ; 59.469,-19.169 59.85,-19.169 ; 59.469,-19.144 59.85,-19.144 ; 59.469,-18.382 60.51,-18.382 ; 59.469,-18.357 60.51,-18.357 ; 59.469,-18.331 60.51,-18.331 ; 59.469,-18.306 60.51,-18.306 ; 59.469,-18.28 60.51,-18.28 ; 59.469,-18.255 60.51,-18.255 ; 59.469,-18.23 60.51,-18.23 ; 59.469,-18.204 60.51,-18.204 ; 59.469,-18.179 60.51,-18.179 ; 59.469,-18.153 60.51,-18.153 ; 59.469,-16.299 59.545,-16.299 ; 59.469,-16.274 59.545,-16.274 ; 59.469,-16.248 59.621,-16.248 ; 59.469,-16.223 59.519,-16.223 ; 59.469,-16.198 59.519,-16.198 ; 59.469,-12.108 59.85,-12.108 ; 59.469,-12.083 59.85,-12.083 ; 59.469,-12.057 59.85,-12.057 ; 59.469,-12.032 59.85,-12.032 ; 59.469,-12.007 59.85,-12.007 ; 59.469,-11.981 59.85,-11.981 ; 59.469,-11.956 59.85,-11.956 ; 59.469,-11.93 59.85,-11.93 ; 59.469,-11.905 59.85,-11.905 ; 59.469,-11.88 59.85,-11.88 ; 59.469,-11.854 59.85,-11.854 ; 59.469,-11.829 59.85,-11.829 ; 59.469,-11.803 61.196,-11.803 ; 59.469,-11.778 61.196,-11.778 ; 59.469,-10.076 59.85,-10.076 ; 59.469,-10.051 59.85,-10.051 ; 59.469,-10.025 59.85,-10.025 ; 59.469,-10 59.85,-10 ; 59.469,-9.975 59.85,-9.975 ; 59.469,-9.949 59.85,-9.949 ; 59.469,-9.924 59.85,-9.924 ; 59.469,-9.898 59.85,-9.898 ; 59.469,-9.873 59.85,-9.873 ; 59.469,-9.848 59.85,-9.848 ; 59.469,-9.822 59.85,-9.822 ; 59.469,-9.797 59.85,-9.797 ; 59.519,-15.385 59.672,-15.385 ; 59.519,-15.359 59.672,-15.359 ; 59.596,-16.375 59.672,-16.375 ; 59.596,-16.35 59.672,-16.35 ; 59.672,-16.299 59.9,-16.299 ; 59.672,-16.274 59.9,-16.274 ; 59.697,-15.385 60.053,-15.385 ; 59.697,-15.359 60.053,-15.359 ; 59.824,-22.09 60.154,-22.09 ; 59.824,-22.065 60.154,-22.065 ; 59.824,-22.04 60.154,-22.04 ; 59.824,-22.014 60.154,-22.014 ; 59.824,-21.989 60.154,-21.989 ; 59.824,-21.963 60.154,-21.963 ; 59.824,-21.938 60.154,-21.938 ; 59.824,-21.913 60.154,-21.913 ; 59.824,-21.887 60.154,-21.887 ; 59.824,-21.862 60.154,-21.862 ; 59.824,-21.836 60.154,-21.836 ; 59.824,-21.811 60.154,-21.811 ; 59.824,-20.414 60.154,-20.414 ; 59.824,-20.389 60.154,-20.389 ; 59.824,-20.363 60.154,-20.363 ; 59.824,-20.338 60.154,-20.338 ; 59.824,-20.312 60.154,-20.312 ; 59.824,-20.287 60.154,-20.287 ; 59.824,-20.262 60.154,-20.262 ; 59.824,-20.236 60.154,-20.236 ; 59.824,-20.211 60.154,-20.211 ; 59.824,-20.185 60.154,-20.185 ; 59.824,-20.16 60.154,-20.16 ; 59.824,-20.135 60.154,-20.135 ; 59.824,-20.109 60.154,-20.109 ; 59.824,-20.084 60.154,-20.084 ; 59.824,-20.058 60.154,-20.058 ; 59.824,-20.033 60.154,-20.033 ; 59.824,-20.008 60.154,-20.008 ; 59.824,-19.982 60.154,-19.982 ; 59.824,-19.957 60.154,-19.957 ; 59.824,-19.931 60.154,-19.931 ; 59.824,-19.906 60.154,-19.906 ; 59.824,-19.881 60.154,-19.881 ; 59.824,-19.855 60.154,-19.855 ; 59.824,-19.83 60.154,-19.83 ; 59.824,-19.804 60.154,-19.804 ; 59.824,-19.779 60.154,-19.779 ; 59.824,-19.754 61.831,-19.754 ; 59.824,-19.068 60.51,-19.068 ; 59.824,-19.042 60.51,-19.042 ; 59.824,-19.017 60.51,-19.017 ; 59.824,-18.992 60.51,-18.992 ; 59.824,-18.966 60.51,-18.966 ; 59.824,-18.941 60.51,-18.941 ; 59.824,-18.915 60.51,-18.915 ; 59.824,-18.89 60.51,-18.89 ; 59.824,-18.865 60.51,-18.865 ; 59.824,-18.839 60.51,-18.839 ; 59.824,-18.814 60.51,-18.814 ; 59.824,-18.788 60.51,-18.788 ; 59.824,-18.077 60.51,-18.077 ; 59.824,-18.052 60.51,-18.052 ; 59.824,-18.026 60.51,-18.026 ; 59.824,-18.001 60.51,-18.001 ; 59.824,-17.976 60.51,-17.976 ; 59.824,-17.95 60.51,-17.95 ; 59.824,-17.925 60.51,-17.925 ; 59.824,-17.899 60.51,-17.899 ; 59.824,-17.874 60.51,-17.874 ; 59.824,-17.849 60.51,-17.849 ; 59.824,-17.823 60.51,-17.823 ; 59.824,-17.798 60.51,-17.798 ; 59.824,-13.429 60.154,-13.429 ; 59.824,-13.404 60.154,-13.404 ; 59.824,-13.378 60.154,-13.378 ; 59.824,-13.353 60.154,-13.353 ; 59.824,-13.327 60.154,-13.327 ; 59.824,-13.302 60.154,-13.302 ; 59.824,-13.277 60.154,-13.277 ; 59.824,-13.251 60.154,-13.251 ; 59.824,-13.226 60.154,-13.226 ; 59.824,-13.2 60.154,-13.2 ; 59.824,-13.175 60.154,-13.175 ; 59.824,-13.15 60.154,-13.15 ; 59.824,-13.124 60.154,-13.124 ; 59.824,-13.099 60.154,-13.099 ; 59.824,-13.073 60.154,-13.073 ; 59.824,-13.048 60.154,-13.048 ; 59.824,-13.023 60.154,-13.023 ; 59.824,-12.997 60.154,-12.997 ; 59.824,-12.972 60.154,-12.972 ; 59.824,-12.946 60.154,-12.946 ; 59.824,-12.921 60.154,-12.921 ; 59.824,-12.896 60.154,-12.896 ; 59.824,-12.87 60.154,-12.87 ; 59.824,-12.845 60.154,-12.845 ; 59.824,-12.819 60.154,-12.819 ; 59.824,-12.794 60.154,-12.794 ; 59.824,-12.769 60.154,-12.769 ; 59.824,-12.438 61.501,-12.438 ; 59.824,-12.413 60.51,-12.413 ; 59.824,-12.388 60.51,-12.388 ; 59.824,-12.362 60.51,-12.362 ; 59.824,-12.337 60.51,-12.337 ; 59.824,-12.311 60.51,-12.311 ; 59.824,-12.286 60.51,-12.286 ; 59.824,-12.261 60.51,-12.261 ; 59.824,-12.235 60.51,-12.235 ; 59.824,-12.21 60.51,-12.21 ; 59.824,-12.184 60.51,-12.184 ; 59.824,-12.159 60.51,-12.159 ; 59.824,-11.753 60.84,-11.753 ; 59.824,-11.727 60.84,-11.727 ; 59.824,-11.702 60.84,-11.702 ; 59.824,-11.676 60.84,-11.676 ; 59.824,-11.651 60.84,-11.651 ; 59.824,-11.626 60.84,-11.626 ; 59.824,-11.6 60.84,-11.6 ; 59.824,-11.575 60.84,-11.575 ; 59.824,-11.549 60.84,-11.549 ; 59.824,-11.524 60.84,-11.524 ; 59.824,-11.499 60.84,-11.499 ; 59.824,-11.473 60.84,-11.473 ; 59.824,-11.448 61.501,-11.448 ; 59.9,-16.375 59.926,-16.375 ; 59.9,-16.35 59.926,-16.35 ; 59.926,-15.791 60.078,-15.791 ; 59.926,-15.41 60.129,-15.41 ; 59.977,-16.325 60.002,-16.325 ; 59.977,-16.299 60.053,-16.299 ; 59.977,-16.274 60.053,-16.274 ; 59.977,-16.248 60.053,-16.248 ; 59.977,-15.69 60.053,-15.69 ; 59.977,-15.664 60.053,-15.664 ; 59.977,-15.486 60.002,-15.486 ; 59.977,-15.461 60.154,-15.461 ; 59.977,-15.436 60.154,-15.436 ; 60.002,-15.563 60.078,-15.563 ; 60.053,-15.613 60.129,-15.613 ; 60.053,-15.588 60.129,-15.588 ; 60.053,-15.486 60.205,-15.486 ; 60.078,-15.537 60.231,-15.537 ; 60.078,-15.512 60.231,-15.512 ; 60.129,-15.563 60.231,-15.563 ; 60.154,-19.728 61.831,-19.728 ; 60.154,-19.703 61.831,-19.703 ; 60.154,-19.677 61.831,-19.677 ; 60.154,-19.652 61.831,-19.652 ; 60.154,-19.627 61.831,-19.627 ; 60.154,-19.601 61.831,-19.601 ; 60.154,-19.576 61.831,-19.576 ; 60.154,-19.55 61.831,-19.55 ; 60.154,-19.525 61.831,-19.525 ; 60.154,-19.5 61.831,-19.5 ; 60.154,-19.474 61.831,-19.474 ; 60.154,-19.449 64.472,-19.449 ; 60.154,-15.766 60.231,-15.766 ; 60.154,-15.74 60.231,-15.74 ; 60.154,-15.715 60.307,-15.715 ; 60.154,-15.613 60.281,-15.613 ; 60.154,-15.588 60.281,-15.588 ; 60.154,-12.108 60.51,-12.108 ; 60.154,-12.083 60.51,-12.083 ; 60.154,-12.057 60.51,-12.057 ; 60.154,-12.032 60.51,-12.032 ; 60.154,-12.007 60.51,-12.007 ; 60.154,-11.981 60.51,-11.981 ; 60.154,-11.956 60.51,-11.956 ; 60.154,-11.93 60.51,-11.93 ; 60.154,-11.905 60.51,-11.905 ; 60.154,-11.88 60.51,-11.88 ; 60.154,-11.854 60.51,-11.854 ; 60.154,-11.829 60.51,-11.829 ; 60.154,-10.457 62.186,-10.457 ; 60.154,-10.432 60.84,-10.432 ; 60.154,-10.406 60.84,-10.406 ; 60.154,-10.381 60.84,-10.381 ; 60.154,-10.356 60.84,-10.356 ; 60.154,-10.33 60.84,-10.33 ; 60.154,-10.305 60.84,-10.305 ; 60.154,-10.279 60.84,-10.279 ; 60.154,-10.254 60.84,-10.254 ; 60.154,-10.229 60.84,-10.229 ; 60.154,-10.203 60.84,-10.203 ; 60.154,-10.178 60.84,-10.178 ; 60.154,-10.152 60.84,-10.152 ; 60.154,-10.127 62.517,-10.127 ; 60.154,-10.102 62.517,-10.102 ; 60.205,-15.69 60.307,-15.69 ; 60.205,-15.664 60.307,-15.664 ; 60.205,-15.639 60.281,-15.639 ; 60.231,-16.071 60.281,-16.071 ; 60.231,-16.045 60.281,-16.045 ; 60.231,-16.02 60.281,-16.02 ; 60.281,-15.994 60.307,-15.994 ; 60.281,-15.969 60.307,-15.969 ; 60.281,-15.944 60.307,-15.944 ; 60.281,-14.343 60.51,-14.343 ; 60.358,-14.394 60.51,-14.394 ; 60.358,-14.369 60.51,-14.369 ; 60.434,-14.42 60.51,-14.42 ; 60.459,-22.09 60.84,-22.09 ; 60.459,-22.065 60.84,-22.065 ; 60.459,-22.04 60.84,-22.04 ; 60.459,-22.014 60.84,-22.014 ; 60.459,-21.989 60.84,-21.989 ; 60.459,-21.963 60.84,-21.963 ; 60.459,-21.938 60.84,-21.938 ; 60.459,-21.913 60.84,-21.913 ; 60.459,-21.887 60.84,-21.887 ; 60.459,-21.862 60.84,-21.862 ; 60.459,-21.836 60.84,-21.836 ; 60.459,-21.811 60.84,-21.811 ; 60.459,-21.786 60.84,-21.786 ; 60.459,-21.76 60.84,-21.76 ; 60.459,-21.735 60.84,-21.735 ; 60.459,-21.709 60.84,-21.709 ; 60.459,-21.684 60.84,-21.684 ; 60.459,-21.659 60.84,-21.659 ; 60.459,-21.633 60.84,-21.633 ; 60.459,-21.608 60.84,-21.608 ; 60.459,-21.582 60.84,-21.582 ; 60.459,-21.557 60.84,-21.557 ; 60.459,-21.532 60.84,-21.532 ; 60.459,-21.506 60.84,-21.506 ; 60.459,-21.481 60.84,-21.481 ; 60.459,-21.455 60.84,-21.455 ; 60.459,-21.43 60.84,-21.43 ; 60.459,-21.405 60.84,-21.405 ; 60.459,-21.379 60.84,-21.379 ; 60.459,-21.354 60.84,-21.354 ; 60.459,-21.328 60.84,-21.328 ; 60.459,-21.303 60.84,-21.303 ; 60.459,-21.278 60.84,-21.278 ; 60.459,-21.252 60.84,-21.252 ; 60.459,-21.227 60.84,-21.227 ; 60.459,-21.201 60.84,-21.201 ; 60.459,-21.176 60.84,-21.176 ; 60.459,-21.151 60.84,-21.151 ; 60.459,-21.125 60.84,-21.125 ; 60.459,-21.1 61.145,-21.1 ; 60.459,-21.074 61.145,-21.074 ; 60.459,-20.414 61.831,-20.414 ; 60.459,-20.389 61.831,-20.389 ; 60.459,-20.363 61.831,-20.363 ; 60.459,-20.338 61.831,-20.338 ; 60.459,-20.312 61.831,-20.312 ; 60.459,-20.287 61.831,-20.287 ; 60.459,-20.262 61.831,-20.262 ; 60.459,-20.236 61.831,-20.236 ; 60.459,-20.211 61.831,-20.211 ; 60.459,-20.185 61.831,-20.185 ; 60.459,-20.16 61.831,-20.16 ; 60.459,-20.135 61.831,-20.135 ; 60.459,-20.109 61.831,-20.109 ; 60.459,-20.084 61.831,-20.084 ; 60.459,-20.058 60.84,-20.058 ; 60.459,-20.033 60.84,-20.033 ; 60.459,-20.008 60.84,-20.008 ; 60.459,-19.982 60.84,-19.982 ; 60.459,-19.957 60.84,-19.957 ; 60.459,-19.931 60.84,-19.931 ; 60.459,-19.906 60.84,-19.906 ; 60.459,-19.881 60.84,-19.881 ; 60.459,-19.855 60.84,-19.855 ; 60.459,-19.83 60.84,-19.83 ; 60.459,-19.804 60.84,-19.804 ; 60.459,-19.779 60.84,-19.779 ; 60.459,-19.423 62.186,-19.423 ; 60.459,-19.398 62.186,-19.398 ; 60.459,-19.373 62.186,-19.373 ; 60.459,-19.347 62.186,-19.347 ; 60.459,-19.322 62.186,-19.322 ; 60.459,-19.296 62.186,-19.296 ; 60.459,-19.271 62.186,-19.271 ; 60.459,-19.246 62.186,-19.246 ; 60.459,-19.22 62.186,-19.22 ; 60.459,-19.195 62.186,-19.195 ; 60.459,-19.169 62.186,-19.169 ; 60.459,-19.144 62.186,-19.144 ; 60.459,-18.738 61.831,-18.738 ; 60.459,-18.712 61.831,-18.712 ; 60.459,-18.687 61.831,-18.687 ; 60.459,-18.661 61.831,-18.661 ; 60.459,-18.636 61.831,-18.636 ; 60.459,-18.611 61.831,-18.611 ; 60.459,-18.585 61.831,-18.585 ; 60.459,-18.56 61.831,-18.56 ; 60.459,-18.534 61.831,-18.534 ; 60.459,-18.509 61.831,-18.509 ; 60.459,-18.484 61.831,-18.484 ; 60.459,-18.458 61.831,-18.458 ; 60.459,-17.747 61.145,-17.747 ; 60.459,-17.722 61.145,-17.722 ; 60.459,-17.696 61.196,-17.696 ; 60.459,-17.671 61.196,-17.671 ; 60.459,-17.645 61.196,-17.645 ; 60.459,-17.62 61.196,-17.62 ; 60.459,-17.595 61.145,-17.595 ; 60.459,-17.569 61.145,-17.569 ; 60.459,-17.544 61.145,-17.544 ; 60.459,-17.518 61.196,-17.518 ; 60.459,-17.493 61.196,-17.493 ; 60.459,-17.468 61.196,-17.468 ; 60.459,-14.47 60.51,-14.47 ; 60.459,-14.445 60.51,-14.445 ; 60.459,-14.089 61.196,-14.089 ; 60.459,-14.064 61.196,-14.064 ; 60.459,-14.039 61.145,-14.039 ; 60.459,-14.013 61.145,-14.013 ; 60.459,-13.988 61.145,-13.988 ; 60.459,-13.962 61.145,-13.962 ; 60.459,-13.937 61.145,-13.937 ; 60.459,-13.912 61.145,-13.912 ; 60.459,-13.886 61.145,-13.886 ; 60.459,-13.861 61.145,-13.861 ; 60.459,-13.835 61.145,-13.835 ; 60.459,-13.81 61.145,-13.81 ; 60.459,-13.429 61.196,-13.429 ; 60.459,-13.404 61.196,-13.404 ; 60.459,-13.378 61.196,-13.378 ; 60.459,-13.353 61.145,-13.353 ; 60.459,-13.327 61.196,-13.327 ; 60.459,-13.302 61.196,-13.302 ; 60.459,-13.277 61.196,-13.277 ; 60.459,-13.251 61.145,-13.251 ; 60.459,-13.226 61.145,-13.226 ; 60.459,-13.2 61.145,-13.2 ; 60.459,-13.175 61.196,-13.175 ; 60.459,-13.15 61.196,-13.15 ; 60.459,-13.124 61.196,-13.124 ; 60.459,-12.794 61.831,-12.794 ; 60.459,-12.769 61.831,-12.769 ; 60.459,-12.743 61.501,-12.743 ; 60.459,-12.718 61.501,-12.718 ; 60.459,-12.692 61.501,-12.692 ; 60.459,-12.667 61.501,-12.667 ; 60.459,-12.642 61.501,-12.642 ; 60.459,-12.616 61.501,-12.616 ; 60.459,-12.591 61.501,-12.591 ; 60.459,-12.565 61.501,-12.565 ; 60.459,-12.54 61.501,-12.54 ; 60.459,-12.515 61.501,-12.515 ; 60.459,-12.489 61.501,-12.489 ; 60.459,-12.464 61.501,-12.464 ; 60.459,-11.422 61.501,-11.422 ; 60.459,-11.397 61.501,-11.397 ; 60.459,-11.372 61.501,-11.372 ; 60.459,-11.346 61.501,-11.346 ; 60.459,-11.321 61.501,-11.321 ; 60.459,-11.295 61.501,-11.295 ; 60.459,-11.27 61.501,-11.27 ; 60.459,-11.245 61.501,-11.245 ; 60.459,-11.219 61.501,-11.219 ; 60.459,-11.194 61.501,-11.194 ; 60.459,-11.168 61.501,-11.168 ; 60.459,-11.143 61.501,-11.143 ; 60.459,-10.813 61.145,-10.813 ; 60.459,-10.787 61.145,-10.787 ; 60.459,-10.762 61.196,-10.762 ; 60.459,-10.737 61.145,-10.737 ; 60.459,-10.711 61.145,-10.711 ; 60.459,-10.686 61.196,-10.686 ; 60.459,-10.66 61.145,-10.66 ; 60.459,-10.635 61.145,-10.635 ; 60.459,-10.61 61.196,-10.61 ; 60.459,-10.584 61.196,-10.584 ; 60.459,-10.559 61.196,-10.559 ; 60.459,-10.533 61.196,-10.533 ; 60.459,-10.508 61.196,-10.508 ; 60.459,-10.483 61.196,-10.483 ; 60.51,-17.442 61.831,-17.442 ; 60.51,-17.417 61.831,-17.417 ; 60.51,-13.785 62.872,-13.785 ; 60.51,-13.759 62.872,-13.759 ; 60.51,-13.48 63.177,-13.48 ; 60.51,-13.454 63.177,-13.454 ; 60.612,-17.087 60.84,-17.087 ; 60.612,-17.061 60.84,-17.061 ; 60.612,-17.036 60.84,-17.036 ; 60.612,-17.01 60.84,-17.01 ; 60.612,-16.985 60.84,-16.985 ; 60.612,-16.96 60.84,-16.96 ; 60.612,-16.934 60.84,-16.934 ; 60.612,-16.909 60.84,-16.909 ; 60.612,-16.883 60.84,-16.883 ; 60.612,-16.858 60.84,-16.858 ; 60.612,-16.833 60.84,-16.833 ; 60.612,-16.807 60.84,-16.807 ; 60.612,-16.782 61.145,-16.782 ; 60.612,-16.756 61.196,-16.756 ; 60.612,-16.731 61.196,-16.731 ; 60.612,-16.706 61.145,-16.706 ; 60.612,-16.68 61.145,-16.68 ; 60.612,-16.655 61.145,-16.655 ; 60.612,-16.629 61.145,-16.629 ; 60.612,-16.604 61.145,-16.604 ; 60.612,-16.579 61.145,-16.579 ; 60.612,-16.553 61.145,-16.553 ; 60.612,-16.528 61.145,-16.528 ; 60.612,-16.502 61.145,-16.502 ; 60.612,-16.477 61.196,-16.477 ; 60.612,-16.452 64.498,-16.452 ; 60.612,-16.426 64.498,-16.426 ; 60.612,-15.461 61.145,-15.461 ; 60.612,-15.436 61.145,-15.436 ; 60.612,-15.41 60.84,-15.41 ; 60.612,-15.385 60.84,-15.385 ; 60.612,-15.359 60.84,-15.359 ; 60.612,-15.334 60.84,-15.334 ; 60.612,-15.309 60.84,-15.309 ; 60.612,-15.283 60.84,-15.283 ; 60.612,-15.258 60.84,-15.258 ; 60.612,-15.232 60.84,-15.232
